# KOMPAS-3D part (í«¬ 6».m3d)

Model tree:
1. Эскиз:1
2. Операция выдавливания:1
     Расстояние 1 = 3
3. Эскиз:2
4. Операция выдавливания:2
     Расстояние 1 = 78
5. Эскиз:3
6. Операция выдавливания:3
     Расстояние 1 = 3
7. Эскиз:4
8. Операция выдавливания:4
     Расстояние 1 = 4
9. Эскиз:5
10. Операция выдавливания:5
     Расстояние 1 = 4
11. Эскиз:6
12. Вырезать элемент выдавливания:1
     Расстояние 1 = 18.7
13. Эскиз:7
14. Вырезать элемент выдавливания:2
     Расстояние 1 = 118.7
